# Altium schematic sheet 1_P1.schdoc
size 429 x 307 mm; Symbol: Drawing-Symbol_A4; Device: Drawing-Symbol_A4; @Project Name: Framethrower_Denise_2; @Page Count: 1; @Update Date: 2025-08-30; @Create Date: 2025-08-25; @Schematic Name: Schematic1; @Page No: 1; @Page Name: P1; Company: EasyEDA.com; Version: V1.0; Page Size: A4; @Create Time: 09:31:32; @Update Time: 08:33:16; Width: 1655; Height: 1170; Region Start: 1; X Region Count: 6; Y Region Count: 4; Blade Width: 10; Title Block Position: 3; @Board Name: Board1
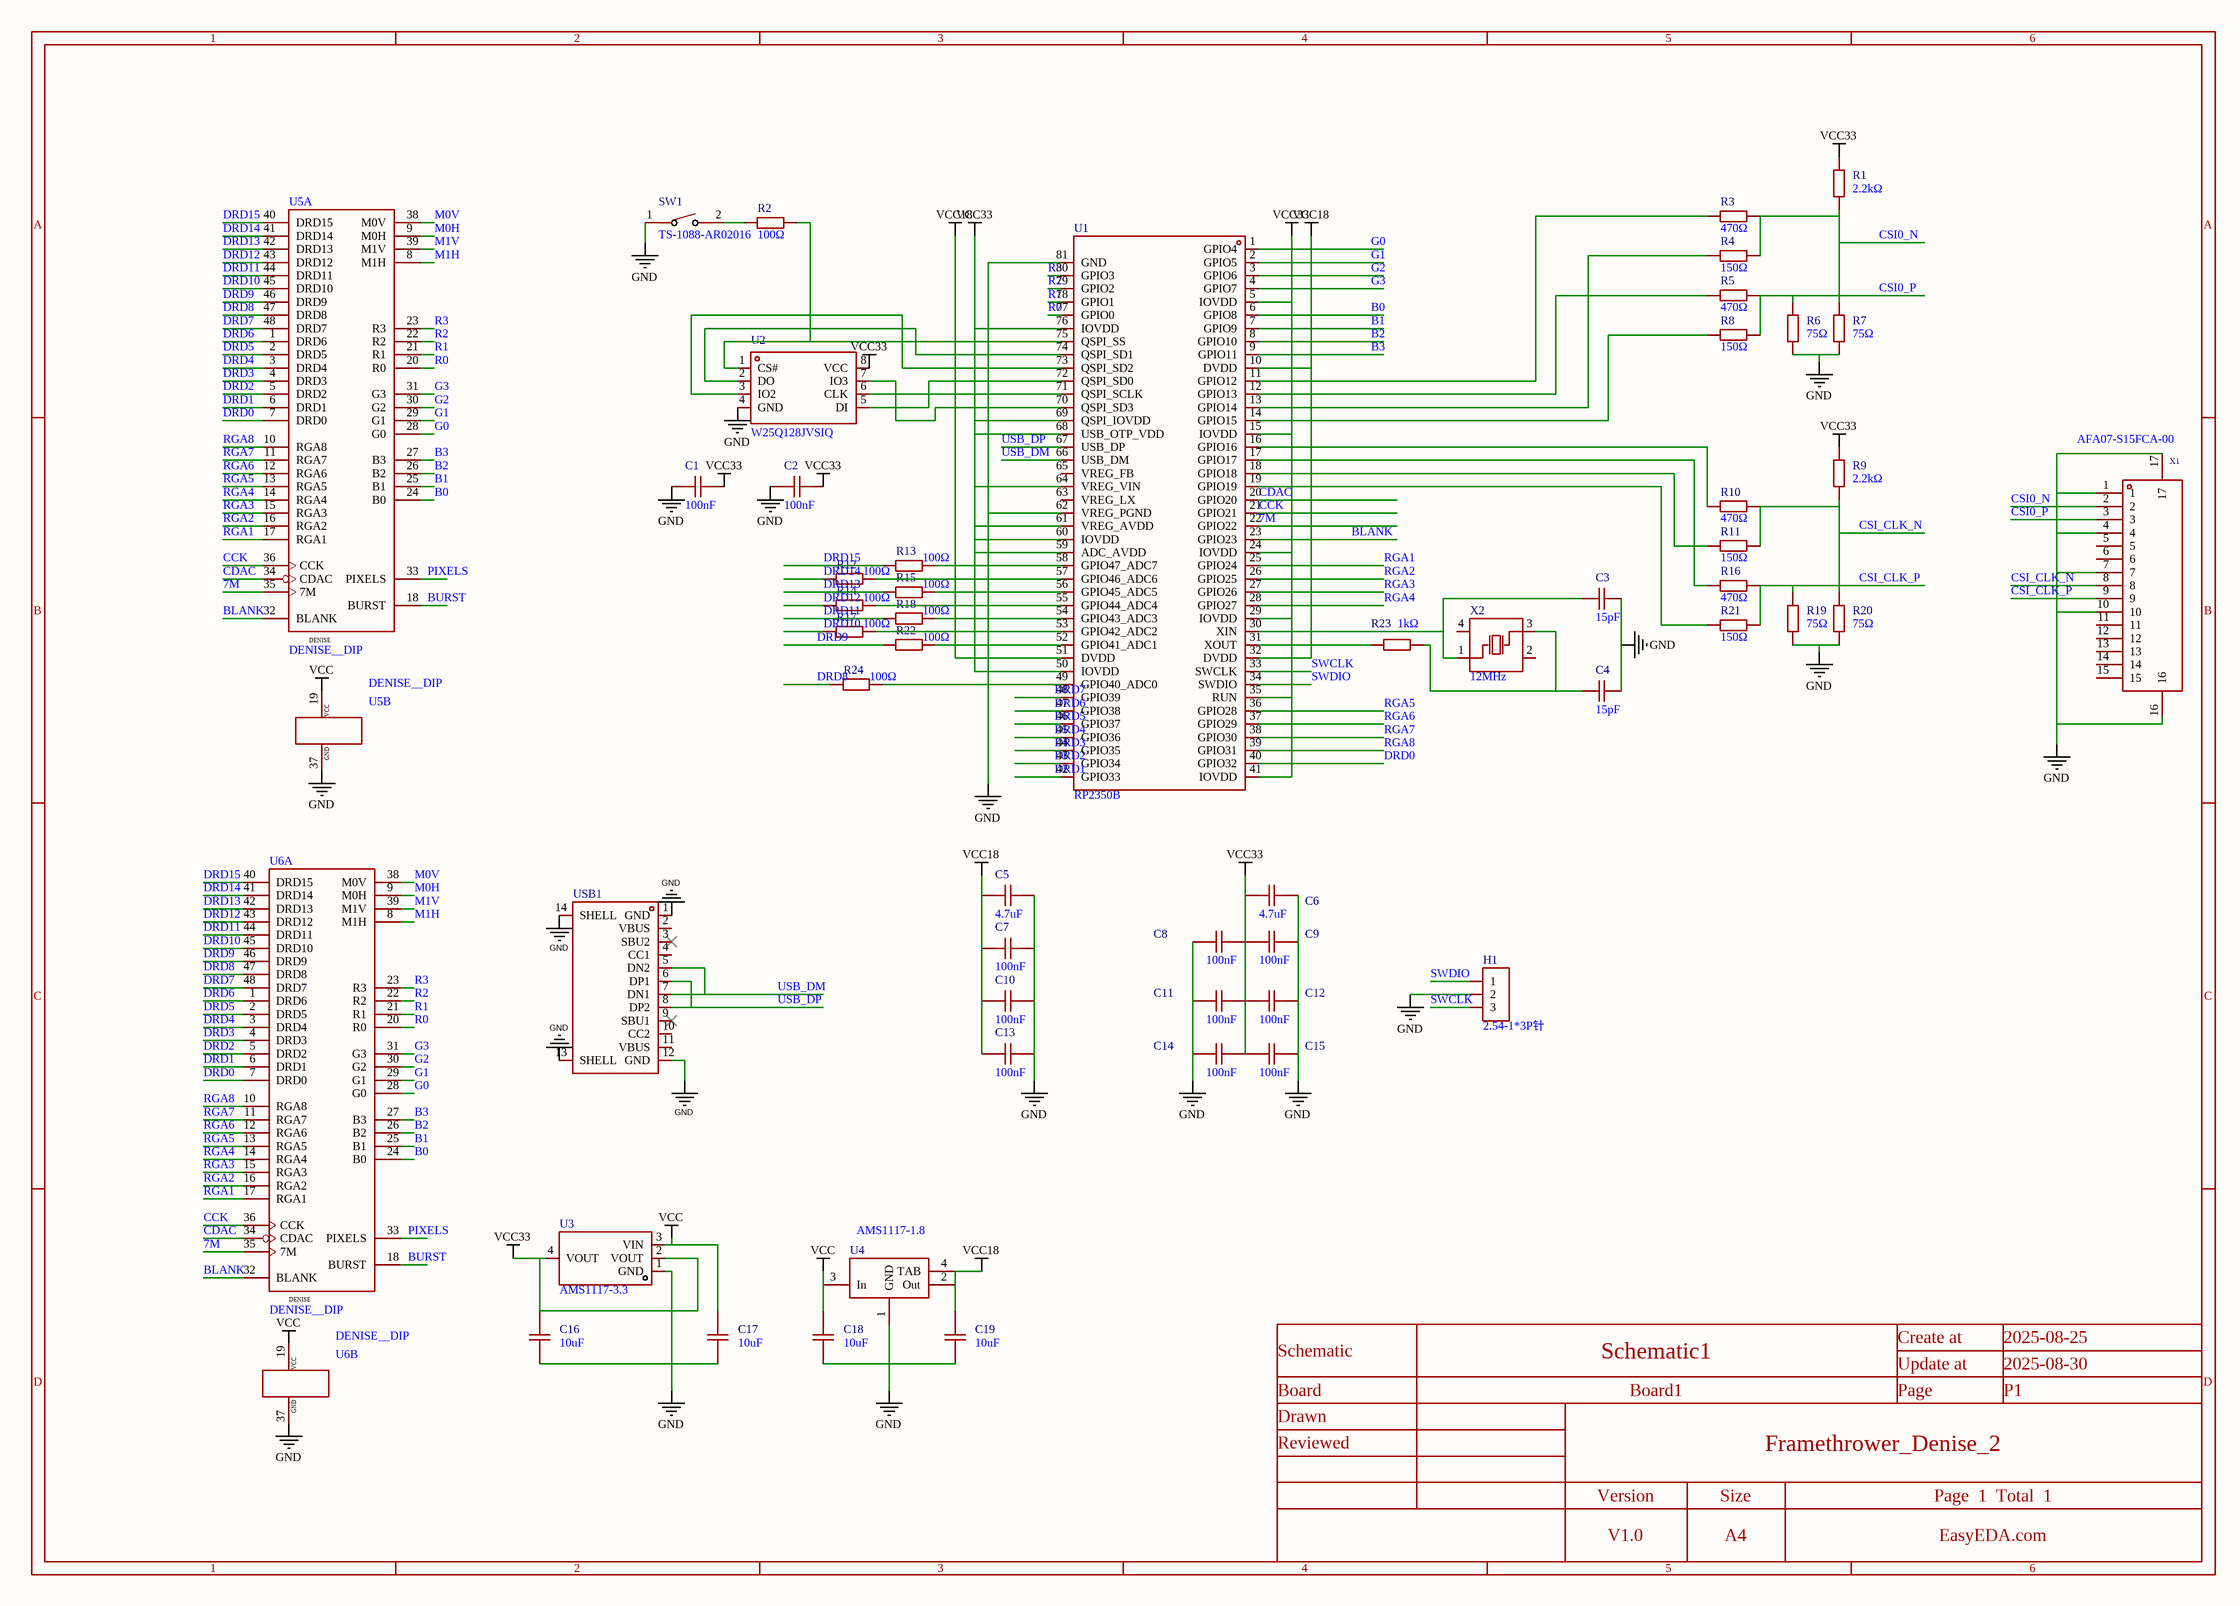
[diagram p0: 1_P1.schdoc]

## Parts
C1  100nF  [C0603]
C2  100nF  [C0603]
C3  15pF  [C0603]
C4  15pF  [C0603]
C5  4.7uF  [C0603]
C6  4.7uF  [C0603]
C7  100nF  [C0603]
C8  100nF  [C0603]
C9  100nF  [C0603]
C10  100nF  [C0603]
C11  100nF  [C0603]
C12  100nF  [C0603]
C13  100nF  [C0603]
C14  100nF  [C0603]
C15  100nF  [C0603]
C16  10uF  [C0603]
C17  10uF  [C0603]
C18  10uF  [C0603]
C19  10uF  [C0603]
H1  2.54-1*3P针  [HDR-TH_3P-P2.54-V-M-1]
R1  2.2kΩ  [R0603]
R2  100Ω  [R0603]
R3  470Ω  [R0603]
R4  150Ω  [R0603]
R5  470Ω  [R0603]
R6  75Ω  [R0603]
R7  75Ω  [R0603]
R8  150Ω  [R0603]
R9  2.2kΩ  [R0603]
R10  470Ω  [R0603]
R11  150Ω  [R0603]
R12  100Ω  [R0603]
R13  100Ω  [R0603]
R14  100Ω  [R0603]
R15  100Ω  [R0603]
R16  470Ω  [R0603]
R17  100Ω  [R0603]
R18  100Ω  [R0603]
R19  75Ω  [R0603]
R20  75Ω  [R0603]
R21  150Ω  [R0603]
R22  100Ω  [R0603]
R23  1kΩ  [R0603]
R24  100Ω  [R0603]
SW1  TS-1088-AR02016  [SW-SMD_L3.9-W3.0-P4.45]
U1  RP2350B  [QFN-80_L10.0-W10.0-P0.40-TL-EP3.4]
U2  W25Q128JVSIQ  [SOIC-8_L5.3-W5.3-P1.27-LS8.0-BL]
U3  AMS1117-3.3  [SOT-223-3_L6.5-W3.4-P2.30-LS7.0-BR]
U4  AMS1117-1.8  [SOT-223-4_L6.5-W3.5-P2.30-LS7.0-BR]
U5  DENISE__DIP  [DIP48-6]  (parts A,B of 2)
U6  DENISE__DIP  [DIP48-6]  (parts A,B of 2)
USB1  TYPE-C 16PIN 2MD(073)  [USB-C-SMD_TYPE-C-6PIN-2MD-073]  (value not drawn)
X1  AFA07-S15FCA-00  [FPC-SMD_15P-P1.00_JS_AFA07-S15XXX]
X2  12MHz  [CRYSTAL-SMD_4P-L3.2-W2.5-BL]

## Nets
GND: C1.1 C2.1 C3.2 C4.2 C5.2 C6.2 C7.2 C8.1 C9.2 C10.2 C11.1 C12.2 C13.2 C14.1 C15.2 C16.1 C17.1 C18.1 C19.1 H1.2 R6.1 R7.1 R12.1 R14.1 R17.1 R19.1 R20.1 SW1.1 U1.53(GPIO42_ADC2) U1.55(GPIO44_ADC4) U1.57(GPIO46_ADC6) U1.62(VREG_PGND) U1.81(GND) U2.4(GND) U3.1(GND) U4.1(GND) U5.37(GND1) U6.37(GND1) USB1.1(GND) USB1.12(GND) USB1.13(SHELL) USB1.14(SHELL) X1.1 X1.4 X1.7 X1.10 X1.16 X1.17
VCC: C17.2 C18.2 U3.3(VIN) U4.3(In) U5.19(VCC1) U6.19(VCC1)
VCC18: C5.1 C7.1 C10.1 C13.1 C19.2 U1.10(DVDD) U1.32(DVDD) U1.51(DVDD) U4.2(Out) U4.4(TAB)
VCC33: C1.2 C2.2 C6.1 C8.2 C9.1 C11.2 C12.1 C14.2 C15.1 C16.2 R1.2 R9.2 U1.5(IOVDD) U1.15(IOVDD) U1.24(IOVDD) U1.29(IOVDD) U1.35(RUN) U1.41(IOVDD) U1.50(IOVDD) U1.59(ADC_AVDD) U1.60(IOVDD) U1.61(VREG_AVDD) U1.64(VREG_VIN) U1.68(USB_OTP_VDD) U1.69(QSPI_IOVDD) U1.76(IOVDD) U2.8(VCC) U3.2(VOUT) U3.4(VOUT)
7M: U1.22(GPIO22) U5.35(7M) U6.35(7M)
B0: U1.6(GPIO8) U5.24(B0) U6.24(B0)
B1: U1.7(GPIO9) U5.25(B1) U6.25(B1)
B2: U1.8(GPIO10) U5.26(B2) U6.26(B2)
B3: U1.9(GPIO11) U5.27(B3) U6.27(B3)
BLANK: U1.23(GPIO23) U5.32(BLANK) U6.32(BLANK)
BURST: U5.18(BURST) U6.18(BURST)
CCK: U1.21(GPIO21) U5.36(CCK) U6.36(CCK)
CDAC: U1.20(GPIO20) U5.34(CDAC) U6.34(CDAC)
CSI0_N: R1.1 R3.2 R4.2 R7.2 X1.2
CSI0_P: R5.2 R6.2 R8.2 X1.3
CSI_CLK_N: R9.1 R10.2 R11.2 R20.2 X1.8
CSI_CLK_P: R16.2 R19.2 R21.2 X1.9
DRD0: U1.40(GPIO32) U5.7(DRD0) U6.7(DRD0)
DRD1: U1.42(GPIO33) U5.6(DRD1) U6.6(DRD1)
DRD2: U1.43(GPIO34) U5.5(DRD2) U6.5(DRD2)
DRD3: U1.44(GPIO35) U5.4(DRD3) U6.4(DRD3)
DRD4: U1.45(GPIO36) U5.3(DRD4) U6.3(DRD4)
DRD5: U1.46(GPIO37) U5.2(DRD5) U6.2(DRD5)
DRD6: U1.47(GPIO38) U5.1(DRD6) U6.1(DRD6)
DRD7: U1.48(GPIO39) U5.48(DRD7) U6.48(DRD7)
DRD8: R24.2 U5.47(DRD8) U6.47(DRD8)
DRD9: R22.2 U5.46(DRD9) U6.46(DRD9)
DRD10: R17.2 U5.45(DRD10) U6.45(DRD10)
DRD11: R18.2 U5.44(DRD11) U6.44(DRD11)
DRD12: R14.2 U5.43(DRD12) U6.43(DRD12)
DRD13: R15.2 U5.42(DRD13) U6.42(DRD13)
DRD14: R12.2 U5.41(DRD14) U6.41(DRD14)
DRD15: R13.2 U5.40(DRD15) U6.40(DRD15)
G0: U1.1(GPIO4) U5.28(G0) U6.28(G0)
G1: U1.2(GPIO5) U5.29(G1) U6.29(G1)
G2: U1.3(GPIO6) U5.30(G2) U6.30(G2)
G3: U1.4(GPIO7) U5.31(G3) U6.31(G3)
M0H: U5.9(M0H) U6.9(M0H)
M0V: U5.38(M0V) U6.38(M0V)
M1H: U5.8(M1H) U6.8(M1H)
M1V: U5.39(M1V) U6.39(M1V)
PIXELS: U5.33(PIXELS) U6.33(PIXELS)
R0: U1.77(GPIO0) U5.20(R0) U6.20(R0)
R1: U1.78(GPIO1) U5.21(R1) U6.21(R1)
R2: U1.79(GPIO2) U5.22(R2) U6.22(R2)
R3: U1.80(GPIO3) U5.23(R3) U6.23(R3)
RGA1: U1.25(GPIO24) U5.17(RGA1) U6.17(RGA1)
RGA2: U1.26(GPIO25) U5.16(RGA2) U6.16(RGA2)
RGA3: U1.27(GPIO26) U5.15(RGA3) U6.15(RGA3)
RGA4: U1.28(GPIO27) U5.14(RGA4) U6.14(RGA4)
RGA5: U1.36(GPIO28) U5.13(RGA5) U6.13(RGA5)
RGA6: U1.37(GPIO29) U5.12(RGA6) U6.12(RGA6)
RGA7: U1.38(GPIO30) U5.11(RGA7) U6.11(RGA7)
RGA8: U1.39(GPIO31) U5.10(RGA8) U6.10(RGA8)
SWCLK: H1.3 U1.33(SWCLK)
SWDIO: H1.1 U1.34(SWDIO)
USB_DM: U1.66(USB_DM) USB1.5(DN2) USB1.7(DN1)
USB_DP: U1.67(USB_DP) USB1.6(DP1) USB1.8(DP2)
NetC3_1: C3.1 U1.30(XIN) X2.1(OSC1)
NetC4_1: C4.1 R23.2 X2.3(OSC2)
NetR2_1: R2.1 U1.75(QSPI_SS) U2.1(CS#)
NetR2_2: R2.2 SW1.2
NetR3_1: R3.1 U1.11(GPIO12)
NetR4_1: R4.1 U1.13(GPIO14)
NetR5_1: R5.1 U1.12(GPIO13)
NetR8_1: R8.1 U1.14(GPIO15)
NetR10_1: R10.1 U1.16(GPIO16)
NetR11_1: R11.1 U1.18(GPIO18)
NetR13_1: R13.1 U1.58(GPIO47_ADC7)
NetR15_1: R15.1 U1.56(GPIO45_ADC5)
NetR16_1: R16.1 U1.17(GPIO17)
NetR18_1: R18.1 U1.54(GPIO43_ADC3)
NetR21_1: R21.1 U1.19(GPIO19)
NetR22_1: R22.1 U1.52(GPIO41_ADC1)
NetR23_1: R23.1 U1.31(XOUT)
NetR24_1: R24.1 U1.49(GPIO40_ADC0)
NetU1_70: U1.70(QSPI_SD3) U2.7(IO3)
NetU1_71: U1.71(QSPI_SCLK) U2.6(CLK)
NetU1_72: U1.72(QSPI_SD0) U2.5(DI)
NetU1_73: U1.73(QSPI_SD2) U2.3(IO2)
NetU1_74: U1.74(QSPI_SD1) U2.2(DO)

Not connected (* = marked no-connect by the designer): U1 63(VREG_LX) 65(VREG_FB); USB1 2(VBUS) 3(SBU2)* 4(CC1) 9(SBU1)* 10(CC2) 11(VBUS); X1 5 6 11 12 13 14 15; X2 2(GND) 4(GND)

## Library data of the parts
C1 C2 C7-C15 = CC0603KRX7R9BB104: Manufacturer: YAGEO(国巨); Add into BOM: yes; Tolerance: ±10%; Voltage Rating: 50V; Temperature Coefficient: X7R
C3 C4 = CL10C150JB8NNNC: Manufacturer: SAMSUNG(三星); Add into BOM: yes; Tolerance: ±5%
C5 C6 = CL10A475KO8NNNC: Manufacturer: SAMSUNG(三星); Add into BOM: yes; Tolerance: ±10%
C16-C19 = CL10A106KP8NNNC: Manufacturer: SAMSUNG(三星); Add into BOM: yes; Tolerance: ±10%
H1 = 2.54-1*3P针: Manufacturer: BOOMELE(博穆精密); Symbol: Header-Male-2.54_1x3; Add into BOM: no; Convert to PCB: yes; Pin Structure: 1x3P; Pitch: 2.54mm; Circluar Pins/Square Pins: Policy; Current Rating (Max): 3A
R1 R9 = 0603WAF2201T5E_C4190: Manufacturer: UNI-ROYAL(厚声); Symbol: 0603WAF5600T5E; Add into BOM: yes; Tolerance: ±1%; Temperature Coefficient: ±100ppm/℃
R2 R12-R15 R17 R18 R22 R24 = 0603WAF1000T5E: Manufacturer: UNI-ROYAL(厚声); Add into BOM: yes; Tolerance: ±1%; Temperature Coefficient: ±200ppm/℃
R3 R5 R10 R16 = 0603WAF4700T5E: Manufacturer: UNI-ROYAL(厚声); Symbol: 0603WAF2400T5E; Add into BOM: yes; Tolerance: ±1%; Power(Watts): 100mW; Voltage-Supply(Max): 75V; Temperature Coefficient: ±100ppm/℃
R4 R8 R11 R21 = 0603WAF1500T5E: Manufacturer: UNI-ROYAL(厚声); Symbol: 0603WAF750JT5E; Add into BOM: yes; Tolerance: ±1%; Temperature Coefficient: ±100ppm/℃
R6 R7 R19 R20 = 0603WAF750JT5E: Manufacturer: UNI-ROYAL(厚声); Symbol: 0603WAF270JT5E; Add into BOM: yes; Tolerance: ±1%; Power(Watts): 100mW; Temperature Coefficient: ±100ppm/℃; Voltage-Supply(Max): 75V
R23 = 0603WAF1001T5E: Manufacturer: UNI-ROYAL(厚声); Add into BOM: yes; Tolerance: ±1%; Temperature Coefficient: ±100ppm/℃
SW1 = TS-1088-AR02016: Manufacturer: XUNPU(讯普); Add into BOM: yes; Circuit: SPST; Actuator Style: Round Button; Operating Force: 160gf; Switch Length: 4mm; Switch Width: 3mm; Switch Height: 2mm; Strike Gundam: 不带; Contact Current: 50mA; Voltage Rating (DC): 12V; Insulation Resistance: 100MΩ; Actuator/Cap Color: Black; Pin Style: SMDSplicing; Mechanical Life: 10万次
U1 = RP2350B_C42415655: Manufacturer: Raspberry Pi(树莓派); Add into BOM: yes
U2 = W25Q128JVSIQ: Manufacturer: WINBOND(华邦); Symbol: W25Q128JVSIQTR; Add into BOM: yes; Interface Type: SPI; Memory Size: 128Mbit; Clock Frequency (fc): 133MHz; Supply Voltage: 2.7V~3.6V; Page Programming Time (Tpp): 700us; Block Erase Time (tBE): 120ms@(32KB); Data Retention - TDR (Year): 20 years
U3 = AMS1117-3.3_C6186: Manufacturer: AMS; Add into BOM: yes; Output Type: Fixed; Voltage - Supply: 16V; Output Voltage: 3.3V; Output Current: 1A; Power Supply Rejection Ratio (PSRR): 72dB@(120Hz); Voltage Dropout: 1.1V@(800mA); standby current: 5mA; Output Configuration: Positive; Number of Outputs: 1
U4 = AMS1117-1.8_C6185: Manufacturer: AMS; Add into BOM: yes; Output Type: Fixed; Voltage - Supply: 15V; Output Voltage: 1.8V; Output Current: 1A; Power Supply Rejection Ratio (PSRR): 75dB@(120Hz); Voltage Dropout: 1.3V@(1A); Output Configuration: Positive electrode; Number of Outputs: 1
U5 U6 = DENISE__DIP: Add into BOM: no; Convert to PCB: yes; Relevance: []
USB1 = TYPE-C 16PIN 2MD(073): Manufacturer: SHOU HAN(首韩); Add into BOM: yes; Gender: 母; Number of Ports: 1; Number of Contacts: 16P; Current Rating - Power (Max): 5A
X1 = AFA07-S15FCA-00: Manufacturer: JS(钜硕电子); Add into BOM: yes; Locking Feature: 抽屉式; Number of Contacts: 15P; Pitch: 1mm; FFC, FCB Thickness: 0.3mm
X2 = X322512MSB4SI: Manufacturer: YXC(扬兴晶振); Add into BOM: yes; Normal temperature Frequency Tolerance: ±10ppm; Load Capacitance: 20pF; Frequency Stability: ±20ppm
